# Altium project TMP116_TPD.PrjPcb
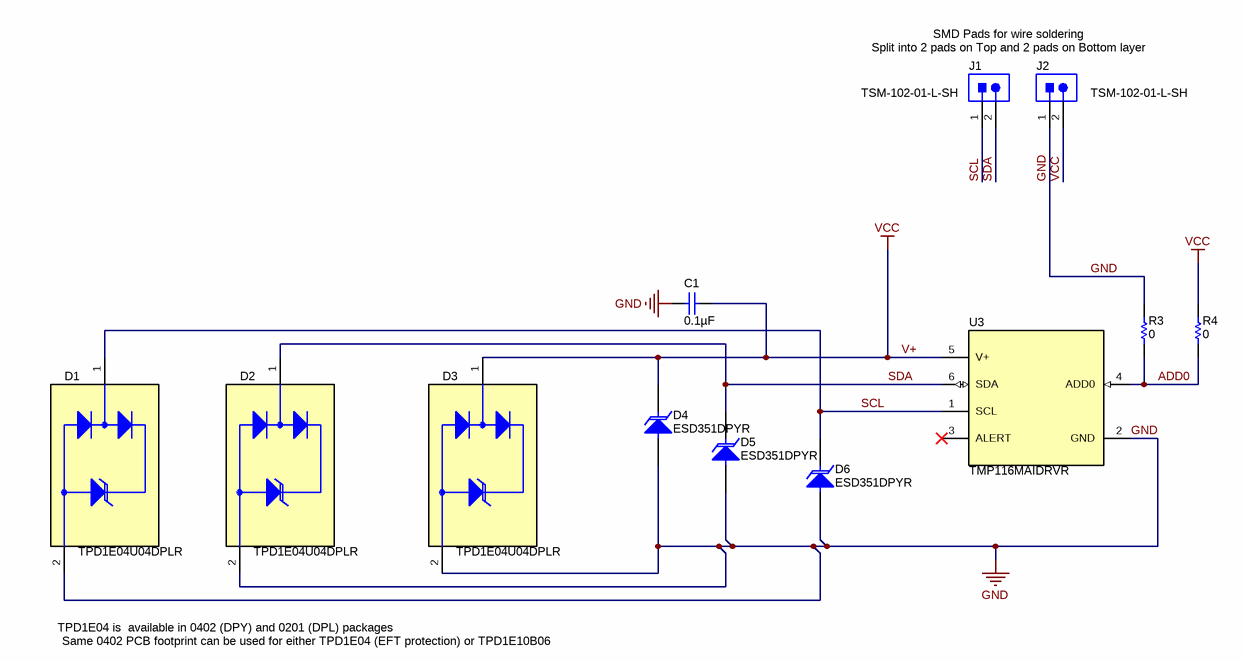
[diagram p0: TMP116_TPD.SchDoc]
CopyrightYear: 2018; EVM_orderable: EVM_shippable; PCB_Layout: a0797195; PCB_Rev: E1; PRJ_Customer: Public Release; PRJ_Engineer: a0797195; PRJ_Number: TIDA-010002; PRJ_Title: TMP116 Digital Temperature Sensor; SCH_Rev: E1; TechSupport: http://www.ti.com/support; TID: TIDA-010002
2 sheets, 20 parts. Net scope: global (net labels, ports and power ports of the same name join across sheets).
Board file: TMP116_TPD.PcbDoc
Sheets:
  TMP116_TPD.SchDoc
  EVM_Hardware.SchDoc

## Sheet TMP116_TPD.SchDoc
size 431 x 279 mm; Date: Not shown in title block; ApprovedBy: Not shown in title block; CheckedBy: Not shown in title block; Author: Not shown in title block; CompanyName: Not shown in title block; Engineer: Not shown in title block; Organization: Not shown in title block; Address1: Not shown in title block; Address2: Not shown in title block; Address3: Not shown in title block; Address4: Not shown in title block; DocumentNumber: 1; Revision: Use project parameter SCH_Rev; SheetNumber: 1; SheetTotal: 2; PageSetup: Record=PageOptions¦CenterHorizontal=True¦CenterVertical=True¦PrintScale=1.00¦XCorrection=1.00¦YCorrection=1.00¦PrintKind=0¦BorderSize=5000000¦LeftOffset=0¦BottomOffset=0¦Orientation=2¦PaperLength=1000¦PaperWidth=1000¦Scale=100¦PaperSource=15¦PrintQuality=600¦MediaType=1¦DitherType=10¦PaperKind=Letter¦PrintScaleMode=1

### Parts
C1  ValueDisplayed: 0.1µF  [0402S]  (hidden comment: GCM155L81E104KE02J)
D1  TPD1E04U04DPLR  [DPY0002A]
D2  TPD1E04U04DPLR  [DPY0002A]
D3  TPD1E04U04DPLR  [DPY0002A]
D4  ESD351DPYR  [DPY0002A]
D5  ESD351DPYR  [DPY0002A]
D6  ESD351DPYR  [DPY0002A]
J1  TSM-102-01-L-SH  [Samtec_TSM-102-01-x-SH]
J2  TSM-102-01-L-SH  [Samtec_TSM-102-01-x-SH]
R3  ValueDisplayed: 0  [0402S]  (hidden comment: CRCW04020000Z0ED)
R4  ValueDisplayed: 0  [0402S]  (hidden comment: CRCW04020000Z0ED)
U3  TMP116MAIDRVR  [DRV0006B]

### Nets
GND: C1.2 D1.2(GND) D2.2(GND) D3.2(GND) D4.2(A) D5.2(A) D6.2(A) J2.1 R3.2 U3.2(GND)
V+: C1.1 D3.1(I/O) D4.1(K) J2.2 R4.2 U3.5(V+)  [also labelled VCC]
ADD0: R3.1 R4.1 U3.4(ADD0)
SCL: D1.1(I/O) D6.1(K) J1.1 U3.1(SCL)
SDA: D2.1(I/O) D5.1(K) J1.2 U3.6(SDA)

Not connected (* = marked no-connect by the designer): U3 3(ALERT)*

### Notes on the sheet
- SMD Pads for wire soldering
- Split into 2 pads on Top and 2 pads on Bottom layer
- TPD1E04 is  available in 0402 (DPY) and 0201 (DPL) packages
- Same 0402 PCB footprint can be used for either TPD1E04 (EFT protection) or TPD1E10B06

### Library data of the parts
C1 = GCM155L81E104KE02J: CAP, CERM, 0.1 µF, 50 V,+/- 10%, X8L, 0402; Manufacturer: MuRata; Polarized: N; CompType: Capacitor; Value: 0.1uF; U/M: EA; Cap_F: 0.0000001; Tolerance_%: 10; VDC_V: 50; Value2: 50V; TaMin_C: -55; TaMax_C: 150; Cap_Case: 0402; AEC Category: Q200; AEC Qualified: Y; AEC Grade: 1; SizeArea_mm2: 0.5; SizeAreaWB_mm2: 3; SizeZ_mm: 0.6
D1-D3 = TPD1E0xU0x: 1-Channel ESD Protection Diode With Low Dynamic Resistance for HDMI 2.0 and USB 3.0, DPL0002A (X2SON-2); Alternate PartNumber: TPD1E04U04DPLT; Alternate Manufacturer: Texas Instruments; SizeAreaWB_mm2: 2.08; U/M: EA; SizeZ_mm: 0.32; SizeX_mm: 0.6; SizeY_mm: 0.3; SizeArea_mm2: 0.18; CompType: IC
D4-D6 = CMP-0084110-1: 1-Channel 30 kV ESD Protection Diode With Low Clamping Voltage in 0402 Package, DPY0002A (X1SON-2); Alternate Manufacturer: Texas Instruments; SizeAreaWB_mm2: 3.2; Rating: Catalog; SizeZ_mm: 0.45; SizeX_mm: 1; SizeY_mm: 0.6; CompType: IC; AEC Qualified: N; AEC Category: Q200
J1 J2 = TSM-102-01-L-SH: Header, 2.54mm, 2x1, Gold with Tin Tail, R/A, SMT; Manufacturer: Samtec; SymbolCreator: a0412235; Pitch_mm: 2.54; Gender: Male; Shrouded: N; Row_Count: 1; Current_A: 5.4; Voltage_V: 475; Cert_CSA: Y
R3 R4 = CRCW04020000Z0ED: RES, 0, 5%, 0.063 W, 0402; Manufacturer: Vishay-Dale; CompType: Resistor; Value: 0; Value_Code: 0000; Tolerance_%: 5; Power_W: 0.063; Value2: 0.063W; VDC_V: 50; TempCo: 200 ppm/C; EIA_Code: E24; U/M: EA; AEC Category: Q200; SizeArea_mm2: 0.5; SizeX_mm: 1; SizeZ_mm: 0.6; Green_Lifecycle: Active; Green_REACh: Passed
U3 = CMP-0077792-1: High-Accuracy, Low-Power, Digital Temperature Sensor With SMBus- and I2C-Compatible Interface, DRV0006B (WSON-6); Alternate PartNumber: TMP116MAIDRVT; Alternate Manufacturer: Texas Instruments; SizeAreaWB_mm2: 9.0; SizeZ_mm: 0.8; SizeX_mm: 2.0; SizeArea_mm2: 4.0; CompType: IC; AEC Qualified: N; AEC Category: Q200

## Sheet EVM_Hardware.SchDoc
size 431 x 279 mm; Date: Not shown in title block; ApprovedBy: Not shown in title block; CheckedBy: Not shown in title block; Author: Not shown in title block; CompanyName: Not shown in title block; Engineer: Not shown in title block; Organization: Not shown in title block; Address1: Not shown in title block; Address2: Not shown in title block; Address3: Not shown in title block; Address4: Not shown in title block; DocumentNumber: 1; Revision: Use project parameter SCH_Rev; SheetNumber: 2; SheetTotal: 2; PageSetup: Record=PageOptions¦CenterHorizontal=True¦CenterVertical=True¦PrintScale=1.00¦XCorrection=1.00¦YCorrection=1.00¦PrintKind=0¦BorderSize=5000000¦LeftOffset=0¦BottomOffset=0¦Orientation=2¦PaperLength=1000¦PaperWidth=1000¦Scale=100¦PaperSource=15¦PrintQuality=600¦MediaType=1¦DitherType=10¦PaperKind=Letter¦PrintScaleMode=1
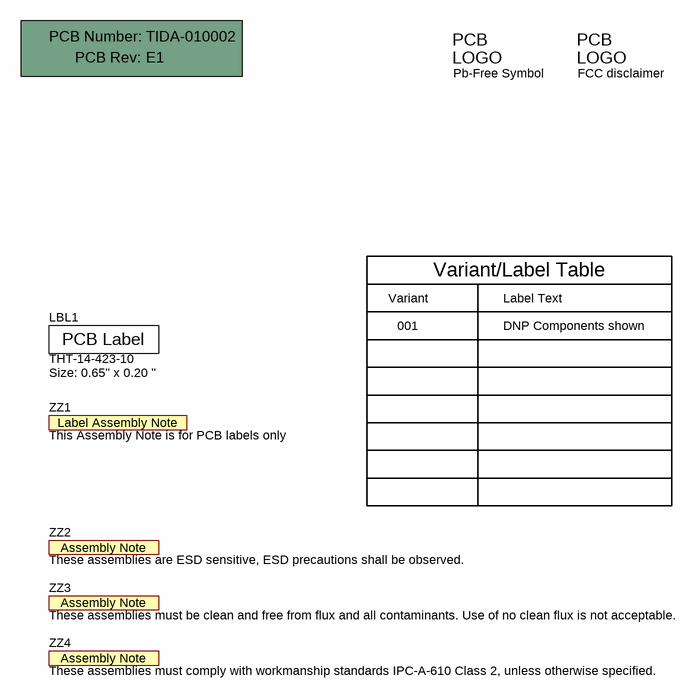
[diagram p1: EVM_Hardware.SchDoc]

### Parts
!PCB  Printed Circuit Board  (value not drawn)  (mechanical)
LBL1  THT-14-423-10  Note: Size: 0.65" x 0.20 "  [Label_650x200]
Logo2  Pb-Free Symbol  [Pb-Free_Overlay_Small]  (no BOM)
Logo3  FCC disclaimer  [FCC_disclaimer]  (no BOM)
ZZ1  This Assembly Note is for PCB labels only  [AssemblyNoteLabel]  (no BOM)
ZZ2  These assemblies are ESD sensitive, ESD precautions shall be observed.  [AssemblyNote]  (no BOM)
ZZ3  These assemblies must be clean and free from flux and all contaminants. Use of no clean flux is not acceptable.  [AssemblyNote]  (no BOM)
ZZ4  These assemblies must comply with workmanship standards IPC-A-610 Class 2, unless otherwise specified.  [AssemblyNote]  (no BOM)

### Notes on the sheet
- Variant
- Variant/Label Table
- Label Text
- 001
- DNP Components shown

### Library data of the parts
!PCB = CMP-0003618-2: Manufacturer: Any; PartNumber: TIDA-010002
LBL1 = CMP-0003625-1: Thermal Transfer Printable Labels, 0.650" W x 0.200" H - 10,000 per roll; Manufacturer: Brady; CompType: Label
Logo2 = CMP-0074839-1: SymbolCreator: a0412235; Library Reference: Logo
Logo3 = CMP-0074847-1: FCC_disclaimer; Library Reference: Logo
ZZ1 = CMP-0003616-3
ZZ2 = CMP-0077236-1
ZZ3 = CMP-0077237-1
ZZ4 = CMP-0077238-1

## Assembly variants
001: not fitted D1 D2 D3 J1 J2 R4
